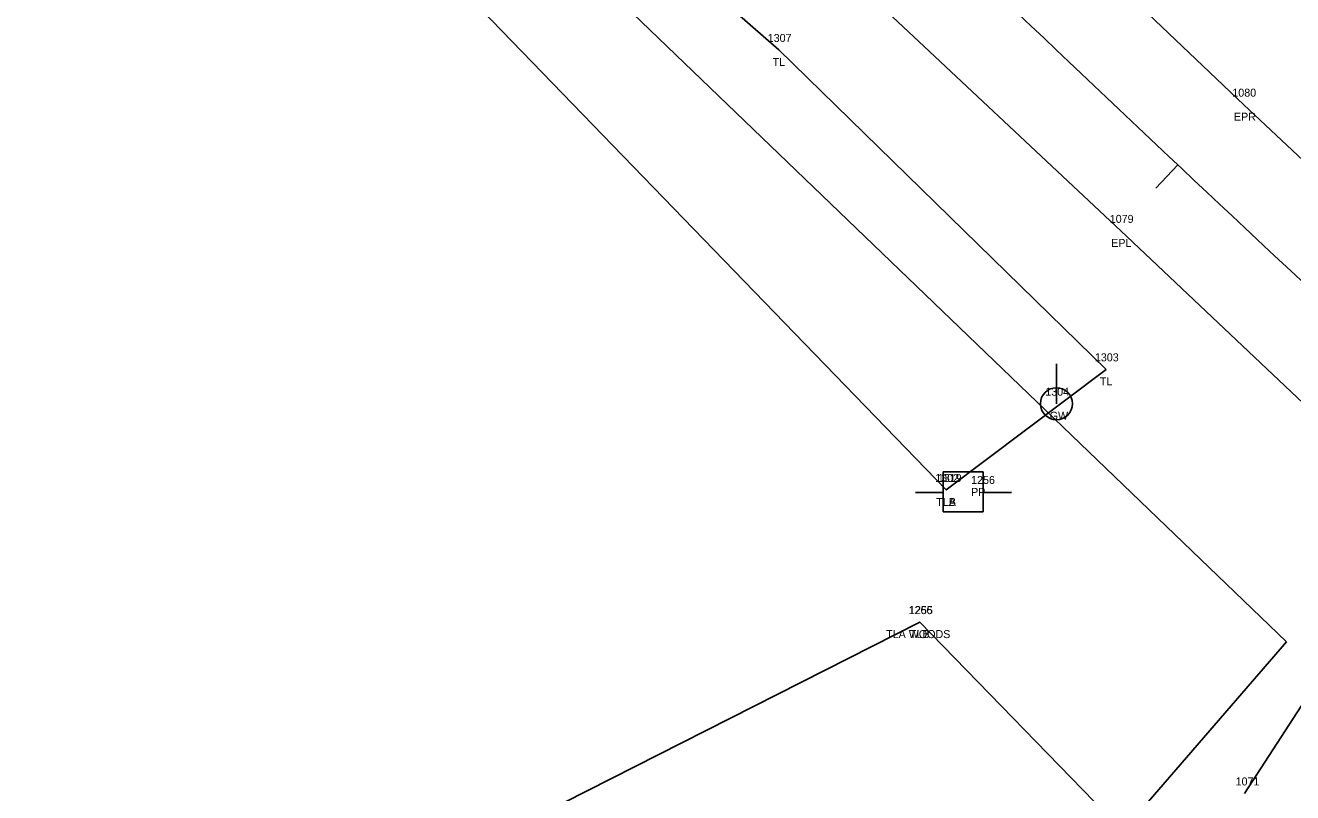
# Model space of a CAD drawing. Extents: x 1812113 to 1819860, y 1177290 to 1181185.
# Drawn here: x 1813849.5 to 1814007.9, y 1178410.7 to 1178506.5 of the extents above; entities that cross this region are included whole.
import ezdxf

# ---------------------------------------------------------------- set-up
doc = ezdxf.new("R2010")
doc.units = 0
for name, color, linetype in [('RD_EX_DV_Prop', 7, 'Continuous'), ('RD_EX_Road', 7, 'Continuous'), ('RD_EX_Road_txCode', 7, 'Continuous'), ('RD_EX_UT', 7, 'Continuous'), ('RD_EX_UT_txCode', 7, 'Continuous'), ('RD_EX_VEG', 7, 'Continuous'), ('RD_EX_VEG_txCode', 7, 'Continuous'), ('RD_HC_CL', 7, 'Continuous'), ('RD_HC_Data_Tic', 7, 'Continuous'), ('RD_SMD_Locator', 7, 'Continuous')]:
    doc.layers.add(name, color=color, linetype=linetype)

msp = doc.modelspace()

# ---------------------------------------------------------------- linework, layer by layer
at = {"layer": 'RD_EX_DV_Prop'}
for p, q in [((1814007.16, 1178429.49), (1813829.73, 1178600.06)), ((1813876.31, 1178278.23), (1814007.16, 1178429.49))]:
    msp.add_line(p, q, dxfattribs=at)
at = {"layer": 'RD_EX_Road'}
for p, q in [((1813986.47, 1178480.85), (1813949.15, 1178515.86)), ((1814015.19, 1178453.67), (1813986.47, 1178480.85)), ((1814001.91, 1178410.56), (1814011.9, 1178425.95))]:
    msp.add_line(p, q, dxfattribs=at)
msp.add_lwpolyline([(1814076.45, 1178427.4), (1814038.86, 1178461.87), (1814001.83, 1178496.62), (1813965.15, 1178531.54), (1813928.08, 1178567.1), (1813892.01, 1178601.23), (1813854.54, 1178636.51), (1813817.44, 1178670.03), (1813779.87, 1178701.64)], dxfattribs=at)
at = {"layer": 'RD_EX_UT'}
for p, q in [((1813978.41, 1178459.26), (1813978.41, 1178464.26)), ((1813969.24, 1178450.74), (1813964.24, 1178450.74)), ((1813964.24, 1178450.74), (1813964.24, 1178445.74)), ((1813969.24, 1178445.74), (1813969.24, 1178450.74)), ((1813960.81, 1178448.18), (1813964.28, 1178448.18)), ((1813969.17, 1178448.18), (1813972.81, 1178448.18)), ((1813964.24, 1178445.74), (1813969.24, 1178445.74))]:
    msp.add_line(p, q, dxfattribs=at)
msp.add_circle((1813978.41, 1178459.26), 2, dxfattribs=at)
at = {"layer": 'RD_EX_VEG'}
for points in [[(1813964.65, 1178448.48), (1813984.61, 1178463.55), (1813943.71, 1178503.46), (1813904.65, 1178537.57), (1813863.79, 1178578.71), (1813833.99, 1178603.93), (1813823.24, 1178594.53), (1813964.65, 1178448.48)], [(1813961.33, 1178431.97), (1813986.04, 1178406.55), (1813953.31, 1178366.71), (1813903.24, 1178307.28), (1813881.24, 1178391.37), (1813961.33, 1178431.97)]]:
    msp.add_lwpolyline(points, dxfattribs=at)
at = {"layer": 'RD_HC_CL'}
msp.add_arc((1817921.84, 1182660.75), 5730.08, 226.33932, 227.720866, dxfattribs=at)
at = {"layer": 'RD_HC_Data_Tic'}
msp.add_line((1813993.57, 1178489.12), (1813990.83, 1178486.21), dxfattribs=at)
at = {"layer": 'RD_SMD_Locator'}
for centre in [(1813943.71, 1178503.46), (1814001.83, 1178496.62), (1813986.47, 1178480.85), (1813984.61, 1178463.55), (1813964.65, 1178448.48), (1813964.65, 1178448.48), (1813961.33, 1178431.97), (1813961.33, 1178431.97)]:
    msp.add_circle(centre, 0.001, dxfattribs=at)

# ---------------------------------------------------------------- texts
at = {"layer": 'RD_EX_Road_txCode'}
for s, p in [('1080', (1814000.4, 1178497.62)), ('EPR', (1814000.6, 1178494.62)), ('1079', (1813985.08, 1178481.85)), ('EPL', (1813985.26, 1178478.85)), ('1071', (1814000.81, 1178411.56))]:
    msp.add_text(s, height=1, dxfattribs=at).set_placement(p)
at = {"layer": 'RD_EX_UT_txCode'}
for s, p in [('1304', (1813977.02, 1178460.26)), ('GW', (1813977.57, 1178457.26)), ('1256', (1813967.75, 1178449.23)), ('PP', (1813967.75, 1178447.73))]:
    msp.add_text(s, height=1, dxfattribs=at).set_placement(p)
at = {"layer": 'RD_EX_VEG_txCode'}
for s, p in [('1307', (1813942.33, 1178504.46)), ('TL', (1813942.94, 1178501.46)), ('1303', (1813983.22, 1178464.55)), ('TL', (1813983.84, 1178461.55)), ('1302', (1813963.27, 1178449.48)), ('1319', (1813963.59, 1178449.48)), ('TLA', (1813963.39, 1178446.48)), ('TLB', (1813963.41, 1178446.48)), ('1266', (1813959.94, 1178432.97)), ('1255', (1813959.99, 1178432.97)), ('TLA WOODS', (1813957.13, 1178429.97)), ('TLB', (1813960.09, 1178429.97))]:
    msp.add_text(s, height=1, dxfattribs=at).set_placement(p)

doc.saveas('drawing.dxf')
